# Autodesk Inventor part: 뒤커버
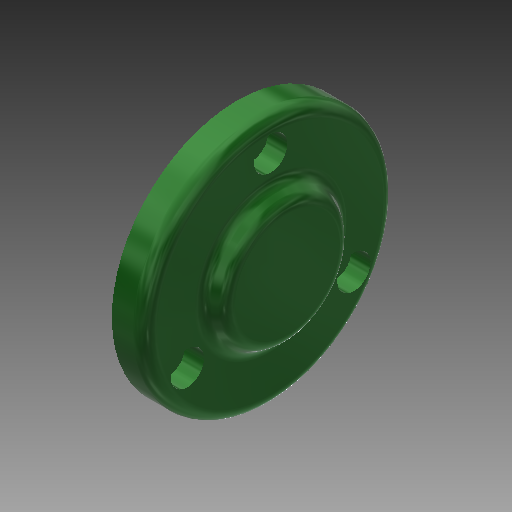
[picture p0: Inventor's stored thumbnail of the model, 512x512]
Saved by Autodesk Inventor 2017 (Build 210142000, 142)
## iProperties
Created: 2015-11
Part Number: 뒤커버
Material: 알루미늄 6061
Document SubType Name: Modeling
Designer: mduedu
Density: 1 g/cm^3
Appearance: 매끄러움 - 짙은 산림 녹색
Author: mduedu
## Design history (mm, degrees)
sketch "스케치5"
  geometry: C1 r 30 at (0, 0); 2 further points
  constraints: 2 coincident, 1 centre point
  dimensions: "d66" = 60 diameter of C1
extrude "돌출2" new body sketch "스케치5" distance "d67" = 8; taper "d68" = 0 deg
sketch "스케치8"
  geometry: C1 r 16.5 at (0, 0); 1 further point
  constraints: 1 centre point, 1 coincident
  dimensions: "d98" = 33 diameter of C1
extrude "돌출4" join sketch "스케치8" distance "d99" = 4; taper "d100" = -30 deg
sketch "스케치6"
  geometry: C1 r 16 at (0, 0); 1 further point
  constraints: 1 centre point, 1 coincident
  dimensions: "d69" = 32 diameter of C1
extrude "돌출3" join sketch "스케치6" distance "d70" = 3; taper "d71" = 0 deg
hole "구멍5" diameter "d74" = 25; stored, may be unused: countersink angle "d78" = 90 deg, drill point angle "d80" = 0 deg; dims "d72" = 10, "d73" = 10, "d75" = 6, "d76" = 4, "d77" = 2, "d79" = 10
fillet "모깎기8" dims "d82" = 3
fillet "모깎기9" dims "d83" = 3
fillet "모깎기10" dims "d84" = 0.3
sketch "스케치7" dims "d85" = 46
  geometry: 3 further points
  constraints: 2 vertical alignment, 1 coincident, 2 other
hole "구멍6" sketch "스케치7" at (0, 23) diameter "d86" = 4.5; stored, may be unused: countersink angle "d90" = 90 deg, drill point angle "d92" = 0 deg; dims "d87" = 6, "d88" = 8, "d89" = 4.6, "d91" = 10
chamfer "모따기2" distance "d102" = 1; stored, may be unused: second distance "d103" = 2, angle "d104" = 45 deg
node "솔리드2"
pattern_circular "원형 패턴3" dims angle "d94" = 360 deg
